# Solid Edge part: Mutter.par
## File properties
Dokumentum tartalom típus: 0
Last saved by: bmolnar
Revision: 76
Sűrűség: 0,000 kg/m^3
Pontosság: 0,990
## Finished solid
Body 1: solid body, 23 faces, 46 edges, 24 vertices.
  Faces by surface: cone 14, plane 8, cylinder 1
  Edges by curve: spline 24, circle 16, line 6
Bounding box of the edges (mm): 5.000 x 15.011 x 13.000, from (0, -7.5056, -6.5) to (5, 7.5056, 6.5).
Cylindrical faces by radius (mm): R3.3235 x1
Conical faces (half-angle, radius in mm at the cone's reference point): 60 deg R3.6618 x2, 60 deg R7.0028 x12
Planar faces by outward normal: +x 1, +z 1, -x 1, -z 1, oblique 4
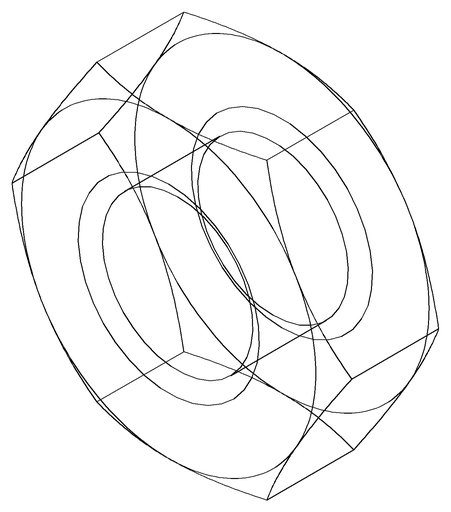
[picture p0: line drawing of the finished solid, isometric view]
